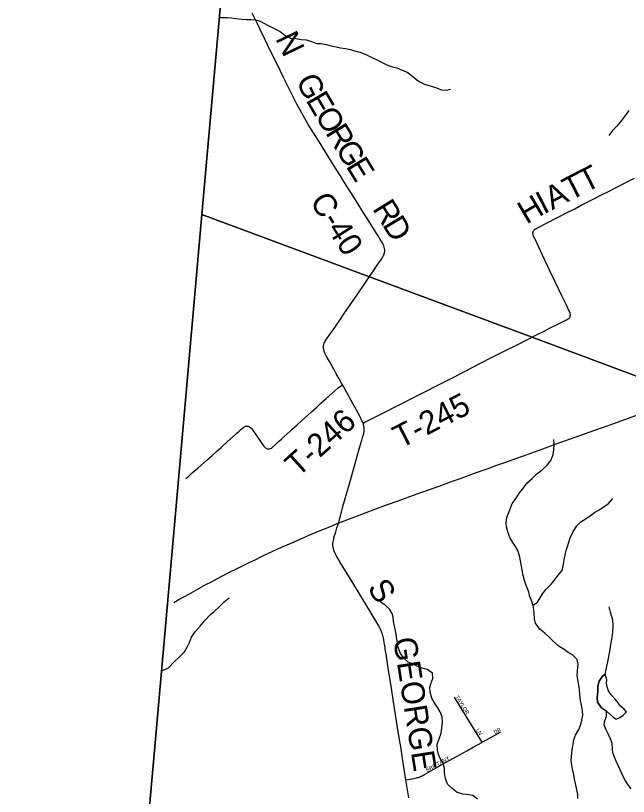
# Model space of a CAD drawing. Extents: x 1442749 to 1756758, y 235267 to 677782.
# Drawn here: x 1545353 to 1553326, y 518732 to 528893 of the extents above; entities that cross this region are included whole.
import ezdxf

# ---------------------------------------------------------------- set-up
doc = ezdxf.new("R2010")
doc.units = 0
for name, color, linetype in [('GM_X_Adjacent_County', 7, 'Continuous'), ('GM_X_County', 7, 'Continuous'), ('GM_X_County_Road', 7, 'Continuous'), ('GM_X_County_Road_Text', 7, 'Continuous'), ('GM_X_Minor_Lake', 7, 'Continuous'), ('GM_X_Minor_River', 7, 'Continuous'), ('GM_X_Township', 7, 'Continuous'), ('GM_X_Township_Road', 7, 'Continuous'), ('GM_X_Township_Road_Text', 7, 'Continuous'), ('GM_X_Township_Subdivision', 7, 'Continuous'), ('GM_X_Township_Subdivision_Text', 7, 'Continuous'), ('GM_X_US_Route', 7, 'Continuous')]:
    doc.layers.add(name, color=color, linetype=linetype)

msp = doc.modelspace()

# ---------------------------------------------------------------- linework, layer by layer
at = {"layer": 'GM_X_Adjacent_County'}
msp.add_lwpolyline([(1551044, 562988), (1549909, 549765), (1549797, 548590), (1549411, 544570), (1549068, 540794), (1548703, 536779), (1548609, 535719), (1548059, 529500), (1548052, 529426), (1547777, 526306), (1547463, 522758), (1547324, 521188), (1546926, 516687), (1546686, 513989), (1546298, 509606), (1545822, 504298), (1545798, 504044), (1545353, 499331)], dxfattribs=at)
at = {"layer": 'GM_X_County'}
msp.add_lwpolyline([(1545353, 499331), (1545798, 504044), (1545822, 504298), (1546298, 509606), (1546686, 513989), (1546926, 516687), (1547324, 521188), (1547463, 522758), (1547777, 526306), (1548052, 529426), (1548059, 529500), (1548609, 535719), (1548703, 536779), (1549068, 540794), (1549411, 544570), (1549797, 548590), (1549909, 549765), (1551044, 562988)], dxfattribs=at)
at = {"layer": 'GM_X_County_Road'}
for points in [[(1550010, 525573), (1550059, 525644), (1550113, 525723), (1550132, 525755), (1550141, 525771), (1550147, 525784), (1550150, 525795), (1550154, 525811), (1550155, 525826), (1550156, 525844), (1550153, 525864), (1550149, 525881), (1550142, 525898), (1550136, 525912), (1550125, 525934), (1550097, 525981), (1550078, 526013), (1550045, 526066), (1549981, 526169), (1549935, 526241), (1549880, 526328), (1549846, 526382), (1549753, 526531), (1549725, 526576), (1549645, 526701), (1549611, 526754), (1549578, 526807), (1549513, 526909), (1549449, 527012), (1549327, 527209), (1549161, 527477), (1549139, 527513), (1549071, 527633), (1549011, 527741), (1548950, 527860), (1548889, 527983), (1548837, 528089), (1548759, 528251), (1548679, 528413), (1548594, 528587), (1548526, 528729), (1548498, 528787), (1548430, 528926)], [(1549605, 524089), (1549594, 524108), (1549562, 524165), (1549525, 524232), (1549496, 524284), (1549480, 524314), (1549436, 524392), (1549394, 524467), (1549378, 524500), (1549373, 524511), (1549369, 524521), (1549365, 524535), (1549361, 524547), (1549359, 524559), (1549358, 524571), (1549358, 524581), (1549360, 524597), (1549363, 524612), (1549368, 524628), (1549375, 524643), (1549381, 524655), (1549389, 524667), (1549407, 524694), (1549450, 524758), (1549504, 524835), (1549579, 524944), (1549627, 525014), (1549696, 525115), (1549765, 525215), (1549813, 525286), (1549877, 525379), (1549966, 525509), (1550010, 525573)], [(1549873, 523590), (1549866, 523607), (1549859, 523621), (1549834, 523671), (1549697, 523924), (1549682, 523950), (1549617, 524066), (1549605, 524089)], [(1549557, 522291), (1549573, 522352), (1549576, 522365), (1549579, 522377), (1549612, 522504), (1549683, 522758), (1549704, 522832), (1549723, 522897), (1549749, 522988), (1549829, 523267), (1549858, 523366), (1549868, 523403), (1549877, 523439), (1549882, 523460), (1549886, 523479), (1549888, 523495), (1549889, 523510), (1549888, 523522), (1549887, 523536), (1549884, 523552), (1549881, 523567), (1549877, 523580), (1549873, 523590)], [(1550432, 518946), (1550387, 519226), (1550363, 519376), (1550340, 519518), (1550323, 519630), (1550271, 519963), (1550234, 520196), (1550206, 520372), (1550173, 520586), (1550169, 520605), (1550166, 520625), (1550162, 520650), (1550159, 520670), (1550156, 520691), (1550152, 520714), (1550150, 520730), (1550147, 520745), (1550145, 520759), (1550142, 520775), (1550138, 520790), (1550134, 520808), (1550131, 520820), (1550126, 520838), (1550121, 520855), (1550117, 520866), (1550112, 520881), (1550105, 520896), (1550097, 520913), (1550087, 520933), (1550077, 520951), (1549966, 521137), (1549813, 521390), (1549670, 521622), (1549571, 521785), (1549554, 521815), (1549535, 521846), (1549525, 521866), (1549515, 521884), (1549509, 521896), (1549506, 521903), (1549501, 521913), (1549497, 521925), (1549493, 521937), (1549489, 521949), (1549487, 521959), (1549484, 521970), (1549483, 521979), (1549482, 521990), (1549482, 521999), (1549481, 522010), (1549482, 522020), (1549482, 522029), (1549483, 522039), (1549485, 522051), (1549488, 522065), (1549491, 522081), (1549495, 522099), (1549517, 522173), (1549534, 522227), (1549546, 522260), (1549557, 522291)], [(1550468, 518714), (1550432, 518946)]]:
    msp.add_lwpolyline(points, dxfattribs=at)
at = {"layer": 'GM_X_Minor_Lake'}
for points in [[(1553024, 520324), (1552989, 520297), (1552944, 520233), (1552926, 520168), (1552927, 520099), (1552921, 520021), (1552924, 519957), (1552977, 519886), (1553040, 519839)], [(1553040, 519839), (1553124, 519769), (1553168, 519736), (1553214, 519759), (1553259, 519788), (1553302, 519832), (1553270, 519866), (1553221, 519905), (1553194, 519950), (1553155, 519999), (1553102, 520052), (1553067, 520105), (1553052, 520145), (1553041, 520203), (1553046, 520251), (1553024, 520324)]]:
    msp.add_lwpolyline(points, dxfattribs=at)
at = {"layer": 'GM_X_Minor_River'}
for points in [[(1548006, 528870), (1548108, 528867), (1548162, 528864), (1548220, 528855), (1548290, 528848), (1548360, 528842), (1548418, 528841), (1548470, 528836), (1548522, 528823), (1548575, 528800), (1548640, 528765), (1548724, 528721), (1548793, 528687), (1548860, 528634), (1548931, 528599), (1548997, 528593), (1549069, 528584), (1549135, 528576), (1549204, 528555), (1549268, 528530), (1549324, 528529), (1549398, 528515), (1549457, 528498), (1549525, 528487), (1549579, 528475), (1549645, 528466), (1549708, 528453), (1549762, 528436), (1549830, 528416), (1549911, 528387), (1549988, 528347), (1550062, 528314), (1550131, 528278), (1550184, 528251), (1550250, 528228), (1550314, 528214), (1550383, 528183), (1550458, 528153), (1550525, 528096), (1550596, 528041), (1550673, 527999), (1550759, 527975), (1550818, 527958), (1550896, 527926), (1550960, 527921), (1551012, 527936)], [(1553333, 527660), (1553286, 527595), (1553236, 527529), (1553175, 527454), (1553121, 527397), (1553072, 527332)], [(1552348, 523182), (1552357, 523240), (1552361, 523316), (1552354, 523377)], [(1552668, 518704), (1552668, 518756), (1552657, 518823), (1552644, 518877), (1552626, 518957), (1552615, 519012), (1552600, 519088), (1552589, 519140), (1552583, 519195), (1552586, 519245), (1552591, 519303), (1552600, 519363), (1552609, 519417), (1552618, 519472), (1552637, 519530), (1552683, 519601), (1552708, 519669), (1552719, 519723), (1552731, 519785), (1552728, 519851), (1552715, 519919), (1552701, 519982), (1552696, 520064), (1552690, 520124), (1552683, 520174), (1552672, 520231), (1552659, 520303), (1552665, 520371), (1552674, 520447), (1552658, 520515), (1552599, 520573), (1552541, 520606), (1552490, 520643), (1552425, 520684), (1552352, 520746), (1552301, 520801), (1552240, 520854), (1552174, 520910), (1552117, 520987), (1552102, 521043), (1552100, 521111), (1552097, 521164), (1552086, 521218), (1552059, 521293), (1552040, 521343), (1552029, 521395), (1551995, 521478), (1551976, 521541), (1551958, 521605), (1551943, 521674), (1551934, 521726), (1551924, 521792), (1551913, 521848), (1551886, 521931), (1551857, 521986), (1551822, 522037), (1551786, 522091), (1551761, 522160), (1551739, 522237), (1551736, 522287), (1551743, 522363), (1551766, 522418), (1551790, 522484), (1551813, 522544), (1551864, 522613), (1551910, 522684), (1551965, 522751), (1552004, 522806), (1552072, 522871), (1552135, 522928), (1552202, 522981), (1552273, 523046), (1552322, 523111), (1552348, 523182)], [(1552085, 521220), (1552143, 521261), (1552178, 521314), (1552209, 521368), (1552258, 521429), (1552324, 521500), (1552373, 521557), (1552410, 521612), (1552463, 521671), (1552478, 521733), (1552492, 521809), (1552505, 521871), (1552518, 521931), (1552534, 521986), (1552551, 522042), (1552568, 522098), (1552609, 522179), (1552653, 522251), (1552706, 522306), (1552777, 522348), (1552832, 522387), (1552885, 522428), (1552945, 522461), (1552996, 522494), (1553069, 522545), (1553124, 522610)], [(1547254, 520364), (1547343, 520406), (1547416, 520481), (1547481, 520542), (1547549, 520612), (1547586, 520672), (1547613, 520733), (1547641, 520805), (1547686, 520870), (1547754, 520947), (1547809, 521018), (1547887, 521099), (1547938, 521138), (1548001, 521200), (1548064, 521265), (1548131, 521318)], [(1550709, 520382), (1550639, 520401), (1550587, 520422), (1550516, 520456), (1550460, 520477), (1550404, 520532), (1550357, 520601), (1550328, 520676), (1550316, 520754), (1550309, 520810), (1550295, 520893), (1550282, 520951), (1550271, 521009), (1550266, 521064), (1550253, 521114), (1550222, 521165), (1550160, 521220), (1550095, 521265)], [(1553363, 518829), (1553324, 518882), (1553287, 518934), (1553253, 519001), (1553203, 519118), (1553166, 519189), (1553144, 519242), (1553123, 519298), (1553120, 519348), (1553113, 519425), (1553094, 519481), (1553068, 519538), (1553035, 519596), (1553012, 519665), (1553021, 519719), (1553040, 519773), (1553040, 519839), (1552977, 519886), (1552924, 519957), (1552921, 520021), (1552927, 520099), (1552926, 520168), (1552944, 520233), (1552989, 520297), (1553024, 520324), (1553046, 520428), (1553057, 520482), (1553070, 520551), (1553086, 520617), (1553093, 520677), (1553100, 520729), (1553116, 520805), (1553125, 520875), (1553129, 520953), (1553122, 521027), (1553107, 521080), (1553094, 521130), (1553076, 521200)], [(1551364, 518698), (1551303, 518743), (1551251, 518754), (1551175, 518762), (1551100, 518783), (1551031, 518835), (1550972, 518890), (1550944, 518963), (1550933, 519045), (1550932, 519097), (1550912, 519172), (1550875, 519226), (1550856, 519277), (1550843, 519333), (1550839, 519411), (1550864, 519481), (1550890, 519555), (1550899, 519621), (1550907, 519699), (1550904, 519769), (1550877, 519833), (1550848, 519884), (1550813, 519937), (1550767, 520010), (1550747, 520088), (1550742, 520147), (1550755, 520198), (1550782, 520266), (1550778, 520336), (1550709, 520382)]]:
    msp.add_lwpolyline(points, dxfattribs=at)
at = {"layer": 'GM_X_Township'}
for points in [[(1570074, 513944), (1565959, 517426), (1564776, 518401), (1563405, 519560), (1563130, 519793), (1562277, 520514), (1559821, 521555), (1557365, 522585), (1554150, 523932), (1552094, 524698), (1549956, 525494), (1547777, 526306), (1548052, 529426), (1548059, 529500), (1548609, 535719), (1548703, 536779), (1549068, 540794), (1549399, 540777), (1554906, 540487), (1558042, 540322), (1561724, 540199), (1566007, 539894), (1574568, 539459)], [(1545353, 499331), (1545798, 504044), (1545822, 504298), (1546298, 509606), (1546686, 513989), (1546926, 516687), (1547324, 521188), (1547463, 522758), (1547777, 526306), (1549956, 525494), (1552094, 524698), (1554150, 523932), (1557365, 522585), (1559821, 521555), (1562277, 520514), (1563130, 519793), (1563405, 519560), (1564776, 518401), (1565959, 517426), (1570074, 513944)]]:
    msp.add_lwpolyline(points, dxfattribs=at)
at = {"layer": 'GM_X_Township_Road'}
for points in [[(1552154, 524750), (1552228, 524788), (1552309, 524828), (1552415, 524881), (1552475, 524911), (1552522, 524934), (1552535, 524942), (1552545, 524948), (1552553, 524954), (1552559, 524961), (1552563, 524966), (1552566, 524971), (1552569, 524980), (1552570, 524985), (1552571, 524992), (1552571, 524999), (1552570, 525006), (1552569, 525013), (1552568, 525019), (1552566, 525025), (1552562, 525036), (1552548, 525066), (1552528, 525107), (1552460, 525246), (1552372, 525427), (1552309, 525561), (1552278, 525627), (1552205, 525784), (1552163, 525870), (1552133, 525935), (1552115, 525973), (1552102, 526000), (1552096, 526015), (1552091, 526024), (1552087, 526037), (1552085, 526046), (1552083, 526054), (1552083, 526063), (1552084, 526069), (1552085, 526076), (1552088, 526084), (1552091, 526090), (1552094, 526096), (1552098, 526101), (1552104, 526108), (1552113, 526115), (1552123, 526120), (1552142, 526132), (1552269, 526195), (1552531, 526330), (1552628, 526380), (1552713, 526424), (1552782, 526459), (1552895, 526516), (1552969, 526554), (1553074, 526609), (1553158, 526652), (1553208, 526678), (1553251, 526699), (1553310, 526730), (1553404, 526777)], [(1549873, 523590), (1549895, 523601), (1549921, 523613), (1549976, 523641), (1550053, 523680), (1550148, 523729), (1550310, 523810), (1550388, 523851), (1550555, 523935), (1550695, 524007), (1550821, 524071), (1550899, 524110), (1551053, 524189), (1551200, 524265), (1551411, 524373), (1551544, 524442), (1551735, 524539), (1551869, 524606), (1552029, 524687), (1552139, 524742), (1552154, 524750)], [(1547568, 522867), (1547605, 522900), (1547656, 522945), (1547724, 523005), (1547840, 523108), (1547910, 523170), (1547975, 523228), (1548022, 523270), (1548055, 523299), (1548107, 523347), (1548186, 523418), (1548230, 523458), (1548260, 523485), (1548282, 523505), (1548306, 523526), (1548317, 523534), (1548326, 523540), (1548335, 523544), (1548345, 523548), (1548353, 523550), (1548363, 523551), (1548372, 523551), (1548379, 523550), (1548387, 523547), (1548395, 523543), (1548402, 523538), (1548411, 523530), (1548421, 523519), (1548433, 523504), (1548453, 523476), (1548478, 523440), (1548548, 523336), (1548569, 523305), (1548581, 523289), (1548595, 523275), (1548606, 523266), (1548614, 523261), (1548624, 523257), (1548633, 523255), (1548641, 523253), (1548648, 523253), (1548655, 523254), (1548667, 523258), (1548677, 523265), (1548689, 523274), (1548700, 523283), (1548739, 523317), (1548774, 523349), (1548810, 523382), (1548849, 523417), (1548886, 523450), (1548923, 523484), (1548952, 523510), (1549016, 523569), (1549074, 523621), (1549154, 523693), (1549201, 523736), (1549272, 523799), (1549326, 523848), (1549394, 523910), (1549504, 524009), (1549546, 524045), (1549562, 524059), (1549578, 524072), (1549593, 524081), (1549605, 524089)]]:
    msp.add_lwpolyline(points, dxfattribs=at)
at = {"layer": 'GM_X_Township_Subdivision'}
for points in [[(1551423, 519437), (1551359, 519541), (1551274, 519676), (1551114, 519935), (1551062, 520022)], [(1551423, 519437), (1551529, 519496), (1551666, 519572)], [(1550432, 518946), (1550506, 518960), (1550534, 518965), (1550553, 518969), (1550567, 518972), (1550582, 518976), (1550593, 518979), (1550603, 518983), (1550611, 518986), (1550621, 518990), (1550634, 518997), (1550649, 519005), (1550673, 519019), (1550766, 519071), (1550939, 519167), (1551099, 519255), (1551222, 519324), (1551308, 519372), (1551417, 519433), (1551423, 519437)]]:
    msp.add_lwpolyline(points, dxfattribs=at)
at = {"layer": 'GM_X_US_Route'}
msp.add_lwpolyline([(1547410, 521256), (1547468, 521289), (1547613, 521370), (1547829, 521488), (1547901, 521526), (1547978, 521567), (1548129, 521644), (1548244, 521701), (1548401, 521779), (1548470, 521812), (1548571, 521861), (1548701, 521922), (1548813, 521974), (1548885, 522006), (1548977, 522046), (1549064, 522085), (1549181, 522135), (1549295, 522184), (1549449, 522246), (1549557, 522291), (1549626, 522319), (1549730, 522359), (1550007, 522462), (1550193, 522530), (1550329, 522579), (1550480, 522634), (1550637, 522690), (1550864, 522771), (1551011, 522824), (1551115, 522861), (1551325, 522937), (1551500, 523000), (1551603, 523037), (1551706, 523074), (1551876, 523135), (1552021, 523187), (1552246, 523267), (1552388, 523319), (1552646, 523412), (1552878, 523494), (1552987, 523533), (1553183, 523604), (1553588, 523749)], dxfattribs=at)

# ---------------------------------------------------------------- texts
at = {"layer": 'GM_X_County_Road_Text'}
for s, rotation, p in [('N', 295.7088, (1548728, 528595)), ('G', 296.8127, (1548993, 528046)), ('E', 300.3126, (1549122, 527793)), ('O', 301.5296, (1549239, 527593)), ('R', 301.5598, (1549377, 527368)), ('G', 301.5582, (1549506, 527158)), ('E', 301.5565, (1549644, 526933)), ('C-40', 302.0909, (1549174, 526477)), ('R', 301.8052, (1549988, 526380)), ('D', 301.03, (1550118, 526172)), ('S', 301.6067, (1549923, 521447)), ('GEORGE', 278.8981, (1550265, 520782))]:
    msp.add_text(s, height=300, rotation=rotation, dxfattribs=at).set_placement(p)
at = {"layer": 'GM_X_Township_Road_Text'}
for s, rotation, p in [('T', 27.1922, (1552768, 526583)), ('T', 27.1851, (1552568, 526480)), ('A', 27.2012, (1552333, 526360)), ('H', 30.7507, (1552001, 526171)), ('I', 27.2441, (1552224, 526303)), ('T-245', 27.0744, (1550362, 523253)), ('T-246', 42.0493, (1549027, 522877))]:
    msp.add_text(s, height=300, rotation=rotation, dxfattribs=at).set_placement(p)
at = {"layer": 'GM_X_Township_Subdivision_Text'}
for s, rotation, p in [('TAYLOR', 301.9996, (1551071, 520026)), ('LN', 304.4969, (1551339, 519595)), ('DR', 27.884, (1551587, 519541)), ('BRITTANY', 29.438, (1550707, 519048))]:
    msp.add_text(s, height=50, rotation=rotation, dxfattribs=at).set_placement(p)

doc.saveas('drawing.dxf')
